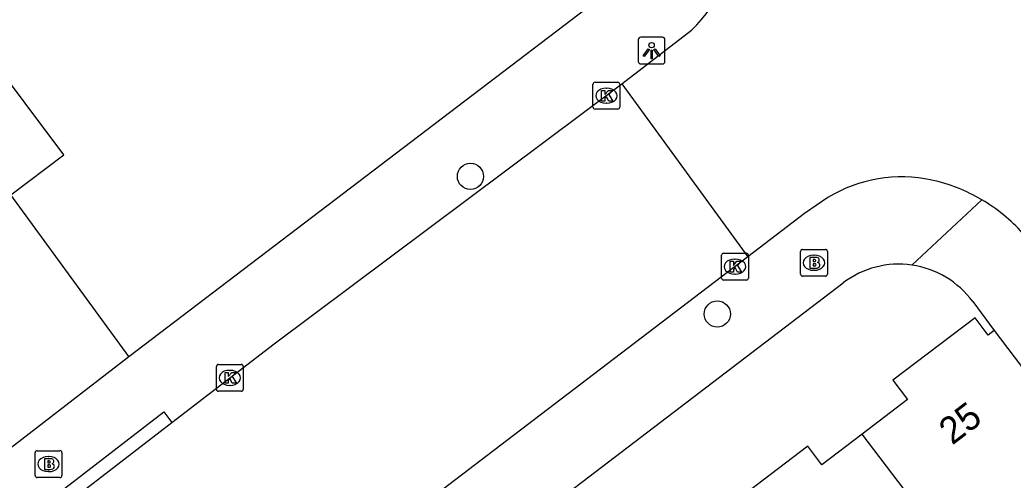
# Model space of a CAD drawing. Extents: x 160037 to 160839, y 385326 to 386441.
# Drawn here: x 160402.85 to 160439.91, y 385775.85 to 385793 of the extents above; entities that cross this region are included whole.
import ezdxf

# ---------------------------------------------------------------- set-up
doc = ezdxf.new("R2010")
doc.units = 0
for name, color, linetype in [('IMGEO_Boom', 7, 'Continuous'), ('IMGEO_Brandkraan', 7, 'Continuous'), ('IMGEO_Kolk', 7, 'Continuous'), ('IMGEO_Lichtpunt', 7, 'Continuous'), ('IMGEO_Pand', 7, 'Continuous'), ('IMGEO_Pand_nummerreeks', 7, 'Continuous'), ('IMGEO_Rijbaan_lokaal_gesloten', 7, 'Continuous'), ('IMGEO_Rijbaan_lokaal_open', 7, 'Continuous'), ('IMGEO_Voetpad_open', 7, 'Continuous')]:
    doc.layers.add(name, color=color, linetype=linetype)

msp = doc.modelspace()

# ---------------------------------------------------------------- linework, layer by layer
at = {"layer": 'IMGEO_Boom'}
for centre in [(160419.666, 385787.169), (160428.877, 385782.038)]:
    msp.add_circle(centre, 0.489, dxfattribs=at)
at = {"layer": 'IMGEO_Brandkraan'}
for p, q in [((160431.983, 385783.521), (160431.983, 385784.373)), ((160432.058, 385784.447), (160432.91, 385784.447)), ((160432.471, 385784.227), (160432.496, 385784.227)), ((160432.984, 385784.373), (160432.984, 385783.521)), ((160432.494, 385783.667), (160432.469, 385783.667)), ((160432.91, 385783.447), (160432.058, 385783.447)), ((160403.423, 385776.017), (160403.423, 385776.869)), ((160403.498, 385776.943), (160404.35, 385776.943)), ((160404.424, 385776.869), (160404.424, 385776.017)), ((160403.911, 385776.723), (160403.936, 385776.723)), ((160403.934, 385776.163), (160403.909, 385776.163)), ((160404.35, 385775.943), (160403.498, 385775.943))]:
    msp.add_line(p, q, dxfattribs=at)
for points in [[(160431.983, 385783.521), (160431.983, 385784.373)], [(160432.058, 385784.447), (160432.91, 385784.447)], [(160432.984, 385784.373), (160432.984, 385783.521)], [(160432.331, 385784.147), (160432.331, 385783.747), (160432.544, 385783.747)], [(160432.562, 385784.147), (160432.331, 385784.147)], [(160432.51, 385784.066), (160432.456, 385784.066), (160432.456, 385783.99)], [(160432.456, 385783.99), (160432.509, 385783.99)], [(160432.518, 385783.914), (160432.456, 385783.914), (160432.456, 385783.833)], [(160432.456, 385783.833), (160432.518, 385783.833)], [(160432.91, 385783.447), (160432.058, 385783.447)], [(160403.423, 385776.017), (160403.423, 385776.869)], [(160403.498, 385776.943), (160404.35, 385776.943)], [(160404.424, 385776.869), (160404.424, 385776.017)], [(160403.771, 385776.643), (160403.771, 385776.243), (160403.984, 385776.243)], [(160404.002, 385776.643), (160403.771, 385776.643)], [(160403.95, 385776.562), (160403.896, 385776.562), (160403.896, 385776.486)], [(160403.896, 385776.486), (160403.949, 385776.486)], [(160403.958, 385776.41), (160403.896, 385776.41), (160403.896, 385776.329)], [(160403.896, 385776.329), (160403.958, 385776.329)], [(160404.35, 385775.943), (160403.498, 385775.943)]]:
    msp.add_lwpolyline(points, dxfattribs=at)
for centre, radius, start, end in [((160432.06, 385784.371), 0.0765, 91.552, 178.448), ((160432.06, 385784.371), 0.0765, 91.552, 178.448), ((160432.908, 385784.371), 0.0765, 1.552, 88.448), ((160432.908, 385784.371), 0.0765, 1.552, 88.448), ((160432.511, 385784.028), 0.0379, 267.8285, 90.9355), ((160432.519, 385783.873), 0.0404, 269.8759, 90.5077), ((160432.566, 385784.002), 0.145, 59.4692, 91.5367), ((160432.591, 385784.049), 0.0922, 285.5137, 58.1501), ((160432.596, 385783.857), 0.105, 301.3115, 78.989), ((160432.06, 385783.523), 0.0765, 181.552, 268.448), ((160432.06, 385783.523), 0.0765, 181.552, 268.448), ((160432.55, 385783.998), 0.251, 268.6676, 293.5347), ((160432.908, 385783.523), 0.0765, 271.552, 358.448), ((160432.908, 385783.523), 0.0765, 271.552, 358.448), ((160403.5, 385776.867), 0.0765, 91.552, 178.448), ((160403.5, 385776.867), 0.0765, 91.552, 178.448), ((160404.348, 385776.867), 0.0765, 1.552, 88.448), ((160404.348, 385776.867), 0.0765, 1.552, 88.448), ((160403.951, 385776.524), 0.0379, 267.8285, 90.9355), ((160404.006, 385776.498), 0.145, 59.4692, 91.5367), ((160404.031, 385776.545), 0.0922, 285.5137, 58.1501), ((160404.036, 385776.353), 0.105, 301.3115, 78.989), ((160403.959, 385776.369), 0.0404, 269.8759, 90.5077), ((160403.99, 385776.494), 0.251, 268.6676, 293.5347), ((160403.5, 385776.019), 0.0765, 181.552, 268.448), ((160403.5, 385776.019), 0.0765, 181.552, 268.448), ((160404.348, 385776.019), 0.0765, 271.552, 358.448), ((160404.348, 385776.019), 0.0765, 271.552, 358.448)]:
    msp.add_arc(centre, radius, start, end, dxfattribs=at)
for centre, major_axis, ratio, start_param, end_param in [((160432.47, 385783.947), (-0.387, 0.002), 0.722429, 4.712389, 7.853982), ((160432.495, 385783.947), (-0.39, 0.002), 0.717154, 1.570796, 4.712389), ((160403.91, 385776.443), (-0.387, 0.002), 0.722429, 4.712389, 7.853982), ((160403.935, 385776.443), (-0.39, 0.002), 0.717154, 1.570796, 4.712389)]:
    msp.add_ellipse(centre, major_axis=major_axis, ratio=ratio, start_param=start_param, end_param=end_param, dxfattribs=at)
at = {"layer": 'IMGEO_Kolk'}
for p, q in [((160424.238, 385789.749), (160424.238, 385790.601)), ((160424.313, 385790.675), (160425.165, 385790.675)), ((160425.239, 385790.601), (160425.239, 385789.749)), ((160424.726, 385790.455), (160424.751, 385790.455)), ((160424.749, 385789.895), (160424.724, 385789.895)), ((160425.165, 385789.675), (160424.313, 385789.675)), ((160429.035, 385783.377), (160429.035, 385784.229)), ((160429.11, 385784.303), (160429.962, 385784.303)), ((160430.036, 385784.229), (160430.036, 385783.377)), ((160429.523, 385784.083), (160429.548, 385784.083)), ((160429.546, 385783.523), (160429.521, 385783.523)), ((160429.962, 385783.303), (160429.11, 385783.303)), ((160410.262, 385780.158), (160411.114, 385780.158)), ((160410.187, 385779.232), (160410.187, 385780.084)), ((160410.675, 385779.938), (160410.7, 385779.938)), ((160411.188, 385780.084), (160411.188, 385779.232)), ((160411.114, 385779.158), (160410.262, 385779.158)), ((160410.698, 385779.378), (160410.673, 385779.378))]:
    msp.add_line(p, q, dxfattribs=at)
for points in [[(160424.238, 385789.749), (160424.238, 385790.601)], [(160424.313, 385790.675), (160425.165, 385790.675)], [(160425.239, 385790.601), (160425.239, 385789.749)], [(160424.559, 385790.375), (160424.682, 385790.375), (160424.682, 385790.224), (160424.812, 385790.375), (160424.976, 385790.375), (160424.83, 385790.224), (160424.983, 385789.975), (160424.831, 385789.975), (160424.746, 385790.139), (160424.682, 385790.072), (160424.682, 385789.975), (160424.559, 385789.975), (160424.559, 385790.375)], [(160425.165, 385789.675), (160424.313, 385789.675)], [(160429.035, 385783.377), (160429.035, 385784.229)], [(160429.11, 385784.303), (160429.962, 385784.303)], [(160430.036, 385784.229), (160430.036, 385783.377)], [(160429.356, 385784.003), (160429.479, 385784.003), (160429.479, 385783.852), (160429.609, 385784.003), (160429.773, 385784.003), (160429.627, 385783.852), (160429.78, 385783.603), (160429.628, 385783.603), (160429.543, 385783.767), (160429.479, 385783.7), (160429.479, 385783.603), (160429.356, 385783.603), (160429.356, 385784.003)], [(160429.962, 385783.303), (160429.11, 385783.303)], [(160410.262, 385780.158), (160411.114, 385780.158)], [(160410.187, 385779.232), (160410.187, 385780.084)], [(160410.508, 385779.858), (160410.631, 385779.858), (160410.631, 385779.707), (160410.761, 385779.858), (160410.925, 385779.858), (160410.779, 385779.707), (160410.932, 385779.458), (160410.78, 385779.458), (160410.695, 385779.622), (160410.631, 385779.555), (160410.631, 385779.458), (160410.508, 385779.458), (160410.508, 385779.858)], [(160411.188, 385780.084), (160411.188, 385779.232)], [(160411.114, 385779.158), (160410.262, 385779.158)]]:
    msp.add_lwpolyline(points, dxfattribs=at)
for centre, start, end in [((160424.315, 385790.599), 91.552, 178.448), ((160424.315, 385790.599), 91.552, 178.448), ((160425.163, 385790.599), 1.552, 88.448), ((160425.163, 385790.599), 1.552, 88.448), ((160424.315, 385789.751), 181.552, 268.448), ((160424.315, 385789.751), 181.552, 268.448), ((160425.163, 385789.751), 271.552, 358.448), ((160425.163, 385789.751), 271.552, 358.448), ((160429.112, 385784.227), 91.552, 178.448), ((160429.112, 385784.227), 91.552, 178.448), ((160429.96, 385784.227), 1.552, 88.448), ((160429.96, 385784.227), 1.552, 88.448), ((160429.112, 385783.379), 181.552, 268.448), ((160429.112, 385783.379), 181.552, 268.448), ((160429.96, 385783.379), 271.552, 358.448), ((160429.96, 385783.379), 271.552, 358.448), ((160410.264, 385780.082), 91.552, 178.448), ((160410.264, 385780.082), 91.552, 178.448), ((160411.112, 385780.082), 1.552, 88.448), ((160411.112, 385780.082), 1.552, 88.448), ((160410.264, 385779.234), 181.552, 268.448), ((160410.264, 385779.234), 181.552, 268.448), ((160411.112, 385779.234), 271.552, 358.448), ((160411.112, 385779.234), 271.552, 358.448)]:
    msp.add_arc(centre, 0.0765, start, end, dxfattribs=at)
for centre, major_axis, ratio, start_param, end_param in [((160424.725, 385790.175), (-0.387, 0.002), 0.722429, 4.712389, 7.853982), ((160424.75, 385790.175), (-0.39, 0.002), 0.717154, 1.570796, 4.712389), ((160429.522, 385783.803), (-0.387, 0.002), 0.722429, 4.712389, 7.853982), ((160429.547, 385783.803), (-0.39, 0.002), 0.717154, 1.570796, 4.712389), ((160410.674, 385779.658), (-0.387, 0.002), 0.722429, 4.712389, 7.853982), ((160410.699, 385779.658), (-0.39, 0.002), 0.717154, 1.570796, 4.712389)]:
    msp.add_ellipse(centre, major_axis=major_axis, ratio=ratio, start_param=start_param, end_param=end_param, dxfattribs=at)
at = {"layer": 'IMGEO_Lichtpunt'}
for p, q in [((160425.928, 385792.262), (160425.928, 385791.455)), ((160425.928, 385792.262), (160425.928, 385791.455)), ((160426.83, 385792.357), (160426.022, 385792.357)), ((160426.83, 385792.357), (160426.022, 385792.357)), ((160426.924, 385791.455), (160426.924, 385792.262)), ((160426.924, 385791.455), (160426.924, 385792.262)), ((160426.022, 385791.361), (160426.83, 385791.361)), ((160426.022, 385791.361), (160426.83, 385791.361))]:
    msp.add_line(p, q, dxfattribs=at)
for points in [[(160426.302, 385791.926), (160426.341, 385791.898), (160426.153, 385791.636), (160426.115, 385791.663), (160426.302, 385791.926)], [(160426.404, 385791.878), (160426.451, 385791.878), (160426.451, 385791.556), (160426.404, 385791.556), (160426.404, 385791.878)], [(160426.514, 385791.898), (160426.552, 385791.925), (160426.739, 385791.663), (160426.7, 385791.635), (160426.514, 385791.898)]]:
    msp.add_lwpolyline(points, dxfattribs=at)
msp.add_circle((160426.427, 385792.06), 0.0994, dxfattribs=at)
for centre, start, end in [((160426.022, 385792.262), 90, 180), ((160426.022, 385792.262), 90, 180), ((160426.83, 385792.262), 0, 90), ((160426.83, 385792.262), 0, 90), ((160426.022, 385791.455), 180, 270), ((160426.022, 385791.455), 180, 270), ((160426.83, 385791.455), 270, 0), ((160426.83, 385791.455), 270, 360)]:
    msp.add_arc(centre, 0.0946, start, end, dxfattribs=at)
at = {"layer": 'IMGEO_Pand'}
for points in [[(160402.512, 385786.485), (160404.494, 385787.977), (160401.599, 385791.824), (160399.617, 385790.332)], [(160439.203, 385781.418), (160438.986, 385781.253), (160438.493, 385781.901), (160435.427, 385779.57), (160435.973, 385778.852), (160434.275, 385777.561)], [(160439.203, 385781.418), (160444.229, 385774.806)], [(160434.275, 385777.561), (160432.774, 385776.42), (160432.251, 385777.109), (160428.974, 385774.619)], [(160439.255, 385771.019), (160434.275, 385777.561)]]:
    msp.add_lwpolyline(points, dxfattribs=at)
at = {"layer": 'IMGEO_Rijbaan_lokaal_gesloten'}
for points in [[(160408.525, 385777.99), (160412.341, 385780.93), (160425.32, 385790.614)], [(160425.32, 385790.614), (160430.014, 385784.168)], [(160430.014, 385784.168), (160420.803, 385777.146), (160400.437, 385761.634), (160385.133, 385750), (160358.201, 385729.526)], [(160403.685, 385774.26), (160408.525, 385777.99)]]:
    msp.add_lwpolyline(points, dxfattribs=at)
at = {"layer": 'IMGEO_Rijbaan_lokaal_open'}
for points in [[(160425.32, 385790.614), (160427.919, 385792.615)], [(160406.915, 385780.456), (160402.512, 385786.485)], [(160432.998, 385786.381), (160432.128, 385785.779), (160430.014, 385784.168)], [(160401.383, 385776.193), (160406.915, 385780.456)]]:
    msp.add_lwpolyline(points, dxfattribs=at)
for centre, radius, start, end in [((160423.583, 385796.952), 6.133, 314.993, 355.6203), ((160435.762, 385781.798), 5.352, 77.9963, 121.096), ((160435.475, 385780.735), 6.452, 59.5342, 77.4661), ((160435.469, 385780.733), 6.457, 41.9729, 59.4975)]:
    msp.add_arc(centre, radius, start, end, dxfattribs=at)
at = {"layer": 'IMGEO_Voetpad_open'}
for points in [[(160406.915, 385780.456), (160424.865, 385794.109)], [(160438.746, 385786.296), (160436.134, 385783.862)], [(160359.486, 385726.76), (160389.993, 385750), (160433.573, 385783.199)], [(160438.405, 385782.504), (160439.203, 385781.418)], [(160403.685, 385774.26), (160403.38, 385774.656), (160408.22, 385778.386), (160408.525, 385777.99)]]:
    msp.add_lwpolyline(points, dxfattribs=at)
for centre, radius, start, end in [((160435.648, 385780.463), 3.434, 81.858, 127.1706), ((160435.647, 385780.47), 3.426, 36.4076, 81.8358)]:
    msp.add_arc(centre, radius, start, end, dxfattribs=at)

# ---------------------------------------------------------------- texts
at = {"layer": 'IMGEO_Pand_nummerreeks'}
msp.add_text('25', height=1, rotation=37.2948, dxfattribs=at).set_placement((160437.641, 385777.129))

doc.saveas('drawing.dxf')
